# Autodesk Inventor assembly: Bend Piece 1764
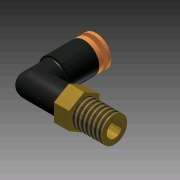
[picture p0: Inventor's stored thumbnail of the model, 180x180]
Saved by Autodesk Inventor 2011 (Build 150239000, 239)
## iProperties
Created: 2010-02
Part Number: Bend Piece 1764
Document SubType Name: Assembly
Designer: jgehrig
Author: jgehrig
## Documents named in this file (4)
- R:\CAD Archives\Pnewmatics\Pnematics Bend Piece\Bend Piece 1764.iam
- R:\CAD Archives\Pnewmatics\Pnematics Bend Piece\Bend Piece.ipt
- R:\CAD Archives\Pnewmatics\Pnematics Bend Piece\pnematic screw part .ipt
- R:\CAD Archives\Pnewmatics\pnewmatic screw\pnematic screw part 2.ipt
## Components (3 placed, 3 different names)
1. Bend Piece:1 — Insert:1, Insert:2
2. pnematic screw part :1 — Insert:2
3. pnematic screw part 2:1 — Insert:1
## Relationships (2: Insert 2)
- Insert:1: Bend Piece:1 ↔ pnematic screw part 2:1
- Insert:2: Bend Piece:1 ↔ pnematic screw part :1
